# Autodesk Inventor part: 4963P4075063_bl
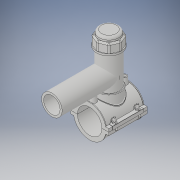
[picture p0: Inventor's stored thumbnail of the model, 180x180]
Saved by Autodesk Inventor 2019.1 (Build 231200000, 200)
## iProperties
Created: 2017-07
Part Number: 4963P4075063_bl
Material: Generic
Document SubType Name: Modeling
Designer: KIM
Density: 1 g/cm^3
Appearance: Default
Author: KIM
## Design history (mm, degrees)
derived "4963P4.ipt"
feature "Solid1::4963P4.ipt" dims "ScaleForDerivedMember" = 10
feature "Solid2::4963P4.ipt" dims "ScaleForDerivedMember" = 10
feature "Solid3::4963P4.ipt" dims "ScaleForDerivedMember" = 10
tag "TaggingFeature1"
body "Solid1"
body "Solid2"
body "Solid3"
other parameters: "d0" = 75 [user parameter], "d2" = 117 [user parameter], "d3" = 18.75 [user parameter], "d4" = 118 [user parameter], "d5" = 0 [user parameter], "d6" = 0.1 [user parameter], "d8" = 0 [user parameter], "d19" = 6 [user parameter], "d20" = 6 [user parameter], "d21" = 70.8 [user parameter], "d23" = 0 [user parameter], "d24" = 35.4 [user parameter], "d26" = 0 [user parameter], "d27" = 3 [user parameter], "d28" = 3 [user parameter], "d29" = 3 [user parameter], "d30" = 25 [user parameter], "d31" = 6 [user parameter], "d32" = 0 [user parameter], "d33" = 0 [user parameter], "d34" = 0.6 [user parameter], "d40" = 50.7 [user parameter], "d41" = 75 [user parameter], "d43" = 0 [user parameter], "d45" = 0 [user parameter], "d47" = 119.55 [user parameter], "d70" = 15 [user parameter], "d72" = 0 [user parameter], "d73" = 6 [user parameter], "d75" = 5 [user parameter], "d76" = 0 [user parameter], "d77" = 3.75 [user parameter], "d78" = 67.5 [user parameter], "d79" = 15 [user parameter], "d80" = 47.2 [user parameter], "d82" = 5 deg [user parameter], "d84" = 4 [user parameter], "d85" = 14 [user parameter], "d86" = 0 [user parameter], "d87" = 3 [user parameter], "d88" = 0 [user parameter], "d89" = 1 [user parameter], "d90" = 1 [user parameter], "d91" = 94.4 [user parameter], "d92" = 0 [user parameter], "d93" = 0.5 [user parameter], "d94" = 39.47368 [user parameter], "d96" = 99.45 [user parameter], "d97" = 2.36 [user parameter], "d98" = 0 [user parameter], "d102" = 0.75 [user parameter], "d120" = 140 deg [user parameter], "d121" = 24.228 [user parameter], "d122" = 20 deg [user parameter], "d123" = 195 [user parameter], "d124" = 58.5 [user parameter], "d126" = 0 [user parameter], "d143" = 77.25 [user parameter], "d145" = 17.30769 [user parameter], "d149" = 1.125 [user parameter], "d150" = 19.03846 [user parameter], "d153" = 118 [user parameter], "d154" = 0 [user parameter], "d156" = 48.75 [user parameter], "d157" = 160 deg [user parameter], "d159" = 4.5 [user parameter], "d161" = 1.125 [user parameter], "d162" = 70.8 [user parameter], "d163" = 0 [user parameter], "d164" = 37.5 [user parameter], "d167" = 7.5 [user parameter], "d168" = 47.56098 [user parameter], "d170" = 3.75 [user parameter], "d172" = 0 [user parameter], "d173" = 1 [user parameter], "d175" = 37.5 [user parameter], "d176" = 20 deg [user parameter], "d177" = 5.25 [user parameter], "d178" = 22.5 [user parameter], "d180" = 0 [user parameter], "d183" = 9 [user parameter], "d184" = 4.2 [user parameter], "d185" = 38.35 [user parameter], "d186" = 38.35 [user parameter], "d187" = 48.75 [user parameter], "d188" = 6.75 [user parameter], "d189" = 5.25 [user parameter], "d190" = 0 [user parameter], "d191" = 73.125 [user parameter], "d193" = 8 [user parameter], "d194" = 4.13 [user parameter], "d195" = 90 deg [user parameter], "d197" = 0 [user parameter], "d199" = 0 [user parameter], "d200" = 11.25 [user parameter], "d202" = 0 [user parameter], "d203" = 177 [user parameter], "d204" = 71.25 [user parameter], "d205" = 52.5 [user parameter], "d206" = 63.75 [user parameter], "d207" = 132.75 [user parameter], "d208" = 138.06 [user parameter], "d209" = 164.61 [user parameter], "d210" = 64.5 [user parameter], "d211" = 75 [user parameter], "d213" = 29.25 [user parameter], "d216" = 0 [user parameter], "d217" = 7.5 [user parameter], "d218" = 7.5 [user parameter], "d219" = 1.5 [user parameter], "d222" = 75 [user parameter], "d224" = 0 [user parameter], "d225" = 64 [user parameter], "d226" = 63 [user parameter], "d227" = 50.4 [user parameter], "d228" = 175 [user parameter], "d230" = 4.5 [user parameter], "d_" = 75 [user parameter], "B_" = 117 [user parameter], "L_" = 118 [user parameter]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
